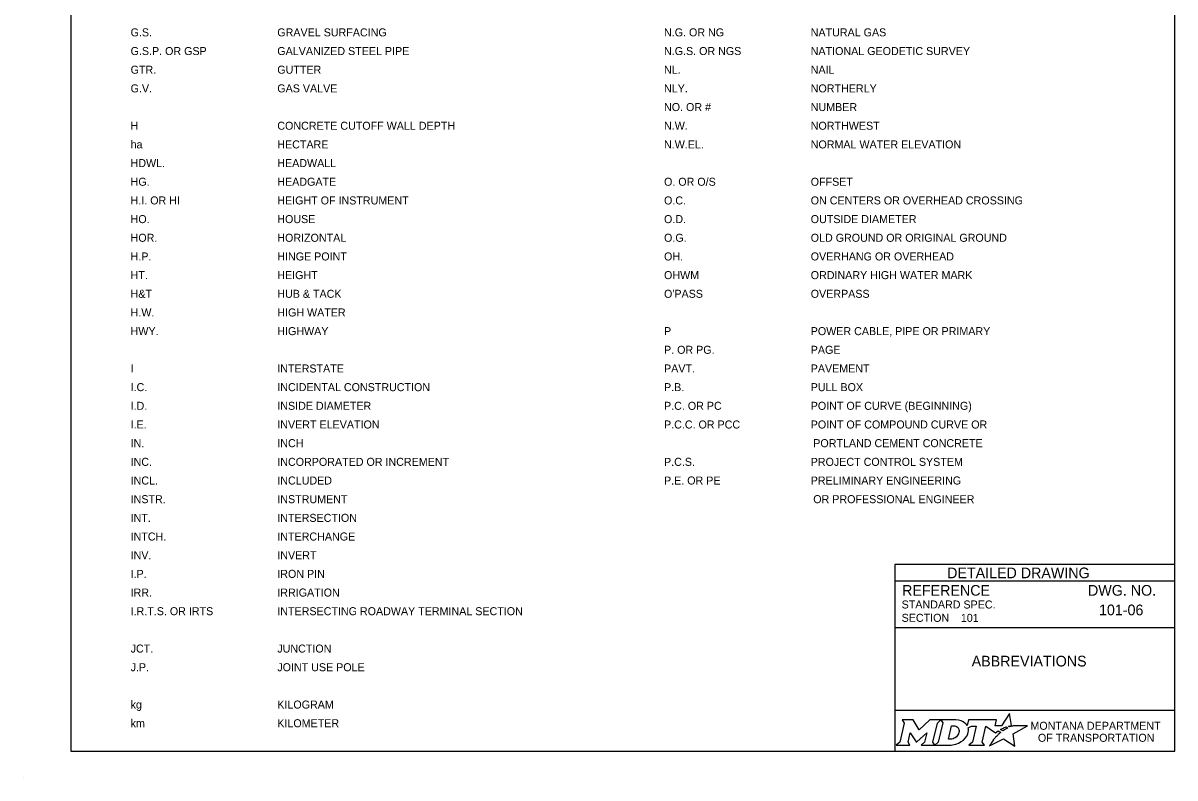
# Model space of a CAD drawing. Extents: x 49991.4 to 50021, y 49987.6 to 50011.4.
# Drawn here: x 49999.98 to 50008.61, y 49999.86 to 50005.52 of the extents above; entities that cross this region are included whole.
import ezdxf

# ---------------------------------------------------------------- set-up
doc = ezdxf.new("R2010")
doc.units = 0
for name, color, linetype in [('Default', 7, 'Continuous'), ('Level 1', 7, 'Continuous'), ('Level 2', 7, 'Continuous'), ('Level 5', 7, 'Continuous')]:
    doc.layers.add(name, color=color, linetype=linetype)

msp = doc.modelspace()

# ---------------------------------------------------------------- linework, layer by layer
at = {"layer": 'Default'}
msp.add_line((50007.719, 50000.7574), (50007.719, 50000.7574), dxfattribs=at)
at = {"layer": 'Level 1'}
msp.add_line((49999.9766, 49999.8624), (49999.9766, 49999.8624), dxfattribs=at)
msp.add_lwpolyline([(50008.6146, 50011.2628), (50000.3356, 50011.2628), (50000.3356, 50000.0624), (50008.6146, 50000.0624)], close=True, dxfattribs=at)
at = {"layer": 'Level 2'}
for p, q in [((50008.6146, 50001.4624), (50006.5146, 50001.4624)), ((50006.5146, 50001.4624), (50006.5146, 50000.0624)), ((50008.6146, 50001.3374), (50006.5146, 50001.3374)), ((50008.2507, 50001.1223), (50008.2507, 50001.1223)), ((50008.6146, 50000.9874), (50006.5146, 50000.9874)), ((50007.0089, 50001.0629), (50007.0089, 50001.0629)), ((50007.5646, 50000.7383), (50007.5646, 50000.7383)), ((50008.6146, 50000.3693), (50006.5146, 50000.3693))]:
    msp.add_line(p, q, dxfattribs=at)
for points in [[(50006.5701, 50000.2974), (50006.5842, 50000.274), (50006.5507, 50000.1307), (50006.525, 50000.1082), (50006.6266, 50000.1082), (50006.6131, 50000.131), (50006.6293, 50000.2011), (50006.673, 50000.1321), (50006.6783, 50000.1321), (50006.7534, 50000.2016), (50006.737, 50000.1305), (50006.7123, 50000.1085), (50006.8139, 50000.1085), (50006.8001, 50000.1318), (50006.8333, 50000.2742)], [(50006.8333, 50000.2742), (50006.8586, 50000.2974), (50006.7762, 50000.2974), (50006.6966, 50000.2244), (50006.6521, 50000.2971), (50006.5701, 50000.2974)], [(50006.9722, 50000.2974), (50006.8586, 50000.2974), (50006.8733, 50000.2745), (50006.8394, 50000.1307), (50006.8139, 50000.1085), (50006.9245, 50000.1085)], [(50007.3771, 50000.2447), (50007.3668, 50000.2503), (50007.3784, 50000.2531), (50007.39, 50000.2551), (50007.3726, 50000.3452), (50007.3131, 50000.2539), (50007.2658, 50000.2532), (50007.2761, 50000.2973), (50007.0669, 50000.2974), (50007.0568, 50000.2549), (50007.051, 50000.2632)], [(50006.9962, 50000.2107), (50006.995, 50000.2026), (50006.9918, 50000.1933), (50006.9876, 50000.1851), (50006.982, 50000.1776), (50006.9755, 50000.1707), (50006.9676, 50000.1644), (50006.9593, 50000.1597), (50006.9502, 50000.1558), (50006.9411, 50000.1535), (50006.9319, 50000.1526), (50006.916, 50000.1526), (50006.9396, 50000.2526), (50006.9556, 50000.2526), (50006.9632, 50000.252), (50006.9708, 50000.2501), (50006.9774, 50000.2471), (50006.9835, 50000.2429), (50006.9883, 50000.2379), (50006.992, 50000.2319), (50006.9947, 50000.2257), (50006.9963, 50000.2183), (50006.9963, 50000.2153), (50006.9962, 50000.2107)], [(50007.0636, 50000.2383), (50007.0882, 50000.2514), (50007.1251, 50000.2514), (50007.0965, 50000.1309), (50007.069, 50000.1082), (50007.1852, 50000.1082), (50007.1682, 50000.1311), (50007.1964, 50000.2513), (50007.2677, 50000.1996), (50007.2888, 50000.2147), (50007.3085, 50000.2038)], [(50007.2527, 50000.1479), (50007.2374, 50000.1235), (50007.2327, 50000.116), (50007.2269, 50000.1074), (50007.2246, 50000.1031), (50007.3299, 50000.1562), (50007.4138, 50000.1011), (50007.4007, 50000.1938), (50007.5076, 50000.2522), (50007.4583, 50000.253), (50007.4282, 50000.2534), (50007.4074, 50000.2537), (50007.4006, 50000.2522), (50007.3957, 50000.251), (50007.3873, 50000.2487), (50007.3771, 50000.2447)], [(50007.3267, 50000.2171), (50007.3243, 50000.2154), (50007.306, 50000.225), (50007.3163, 50000.2307), (50007.3204, 50000.2329), (50007.329, 50000.2369), (50007.3347, 50000.2395), (50007.3426, 50000.2425), (50007.3499, 50000.2452), (50007.3617, 50000.2378), (50007.3577, 50000.2357), (50007.3531, 50000.2332), (50007.3489, 50000.231), (50007.3439, 50000.2281), (50007.342, 50000.227), (50007.3393, 50000.2254), (50007.3368, 50000.224), (50007.3345, 50000.2224), (50007.3319, 50000.2206), (50007.3292, 50000.2188), (50007.3267, 50000.2171)], [(50006.9702, 50000.1158), (50006.9786, 50000.1184), (50006.9916, 50000.1238), (50007.012, 50000.1348)], [(50007.2666, 50000.164), (50007.2666, 50000.164)]]:
    msp.add_lwpolyline(points, dxfattribs=at)
for centre, radius, start, end in [((50006.9953, 50000.219), 0.0709, 339.53292, 15.85821), ((50006.9513, 50000.2363), 0.1183, 300.91025, 339.13831)]:
    msp.add_arc(centre, radius, start, end, dxfattribs=at)
for centre, major_axis, ratio, start_param, end_param in [((50006.9701, 50000.25), (0.0834, -0.0037), 0.568097, 0.61298, 1.570796), ((50007.0257, 50000.2573), (0.0361, -0.0295), 0.469099, 1.225588, 1.570796), ((50007.2974, 50000.1941), (-0.0112, -0.0097), 0.021651, 3.157348, 6.283185), ((50006.9248, 50000.2568), (0, 0.1484), 0.987302, 3.139398, 3.456847), ((50007.2597, 50000.1559), (-0.00694, -0.00806), 0.008222, 0, 3.137361), ((50007.2764, 50000.1742), (-0.0098, -0.0102), 0.016458, 3.141593, 6.279097)]:
    msp.add_ellipse(centre, major_axis=major_axis, ratio=ratio, start_param=start_param, end_param=end_param, dxfattribs=at)

# ---------------------------------------------------------------- texts
for s, height, p in [('G.S.           ', 0.06, (50000.7833, 50005.4226)), ('GRAVEL SURFACING                        ', 0.06, (50001.8833, 50005.4226)), ('N.G. OR NG     ', 0.06, (50004.7833, 50005.4226)), ('NATURAL GAS                             ', 0.06, (50005.8833, 50005.4226)), ('G.S.P. OR GSP  ', 0.06, (50000.7833, 50005.2826)), ('GALVANIZED STEEL PIPE                   ', 0.06, (50001.8833, 50005.2826)), ('N.G.S. OR NGS  ', 0.06, (50004.7833, 50005.2826)), ('NATIONAL GEODETIC SURVEY                ', 0.06, (50005.8833, 50005.2826)), ('GTR.           ', 0.06, (50000.7833, 50005.1426)), ('GUTTER                                  ', 0.06, (50001.8833, 50005.1426)), ('NL.            ', 0.06, (50004.7833, 50005.1426)), ('NAIL                                    ', 0.06, (50005.8833, 50005.1426)), ('G.V.           ', 0.06, (50000.7833, 50005.0026)), ('GAS VALVE                               ', 0.06, (50001.8833, 50005.0026)), ('NLY.           ', 0.06, (50004.7833, 50005.0026)), ('NORTHERLY                               ', 0.06, (50005.8833, 50005.0026)), ('NO. OR #       ', 0.06, (50004.7833, 50004.8626)), ('NUMBER                                  ', 0.06, (50005.8833, 50004.8626)), ('H          ', 0.06, (50000.7833, 50004.7226)), ('CONCRETE CUTOFF WALL DEPTH                              ', 0.06, (50001.8833, 50004.7226)), ('N.W.           ', 0.06, (50004.7833, 50004.7226)), ('NORTHWEST                               ', 0.06, (50005.8833, 50004.7226)), ('ha             ', 0.06, (50000.7833, 50004.5826)), ('HECTARE                                 ', 0.06, (50001.8833, 50004.5826)), ('N.W.EL.        ', 0.06, (50004.7833, 50004.5826)), ('NORMAL WATER ELEVATION                  ', 0.06, (50005.8833, 50004.5826)), ('HDWL.          ', 0.06, (50000.7833, 50004.4426)), ('HEADWALL                                ', 0.06, (50001.8833, 50004.4426)), ('HG.            ', 0.06, (50000.7833, 50004.3026)), ('HEADGATE                                ', 0.06, (50001.8833, 50004.3026)), ('O. OR O/S      ', 0.06, (50004.7833, 50004.3026)), ('OFFSET                                  ', 0.06, (50005.8833, 50004.3026)), ('H.I. OR HI     ', 0.06, (50000.7833, 50004.1626)), ('HEIGHT OF INSTRUMENT                    ', 0.06, (50001.8833, 50004.1626)), ('O.C.           ', 0.06, (50004.7833, 50004.1626)), ('ON CENTERS OR OVERHEAD CROSSING         ', 0.06, (50005.8833, 50004.1626)), ('HO.            ', 0.06, (50000.7833, 50004.0226)), ('HOUSE                                   ', 0.06, (50001.8833, 50004.0226)), ('O.D.           ', 0.06, (50004.7833, 50004.0226)), ('OUTSIDE DIAMETER                        ', 0.06, (50005.8833, 50004.0226)), ('HOR.           ', 0.06, (50000.7833, 50003.8826)), ('HORIZONTAL                              ', 0.06, (50001.8833, 50003.8826)), ('O.G.           ', 0.06, (50004.7833, 50003.8826)), ('OLD GROUND OR ORIGINAL GROUND           ', 0.06, (50005.8833, 50003.8826)), ('H.P.           ', 0.06, (50000.7833, 50003.7426)), ('HINGE POINT                             ', 0.06, (50001.8833, 50003.7426)), ('OH.            ', 0.06, (50004.7833, 50003.7426)), ('OVERHANG OR OVERHEAD                    ', 0.06, (50005.8833, 50003.7426)), ('HT.            ', 0.06, (50000.7833, 50003.6026)), ('HEIGHT                                  ', 0.06, (50001.8833, 50003.6026)), ('OHWM         ', 0.06, (50004.7833, 50003.6026)), ('ORDINARY HIGH WATER MARK                               ', 0.06, (50005.8833, 50003.6026)), ('H&T            ', 0.06, (50000.7833, 50003.4626)), ('HUB & TACK                              ', 0.06, (50001.8833, 50003.4626)), ("O'PASS         ", 0.06, (50004.7833, 50003.4626)), ('OVERPASS                                ', 0.06, (50005.8833, 50003.4626)), ('H.W.           ', 0.06, (50000.7833, 50003.3226)), ('HIGH WATER                              ', 0.06, (50001.8833, 50003.3226)), ('HWY.           ', 0.06, (50000.7833, 50003.1826)), ('HIGHWAY                                 ', 0.06, (50001.8833, 50003.1826)), ('P              ', 0.06, (50004.7833, 50003.1826)), ('POWER CABLE, PIPE OR PRIMARY            ', 0.06, (50005.8833, 50003.1826)), ('P. OR PG.      ', 0.06, (50004.7833, 50003.0426)), ('PAGE                                    ', 0.06, (50005.8833, 50003.0426)), ('INTERSTATE                              ', 0.06, (50001.8833, 50002.9026)), ('I              ', 0.06, (50000.7833, 50002.9026)), ('PAVT.          ', 0.06, (50004.7833, 50002.9026)), ('PAVEMENT                                ', 0.06, (50005.8833, 50002.9026)), ('I.C.           ', 0.06, (50000.7833, 50002.7626)), ('INCIDENTAL CONSTRUCTION                 ', 0.06, (50001.8833, 50002.7626)), ('P.B.           ', 0.06, (50004.7833, 50002.7626)), ('PULL BOX                                ', 0.06, (50005.8833, 50002.7626)), ('I.D.           ', 0.06, (50000.7833, 50002.6226)), ('INSIDE DIAMETER                         ', 0.06, (50001.8833, 50002.6226)), ('P.C. OR PC     ', 0.06, (50004.7833, 50002.6226)), ('POINT OF CURVE (BEGINNING)              ', 0.06, (50005.8833, 50002.6226)), ('I.E.           ', 0.06, (50000.7833, 50002.4826)), ('INVERT ELEVATION                        ', 0.06, (50001.8833, 50002.4826)), ('P.C.C. OR PCC  ', 0.06, (50004.7833, 50002.4826)), ('POINT OF COMPOUND CURVE OR              ', 0.06, (50005.8833, 50002.4826)), ('IN.            ', 0.06, (50000.7833, 50002.3426)), ('INCH                                    ', 0.06, (50001.8833, 50002.3426)), ('   PORTLAND CEMENT CONCRETE             ', 0.06, (50005.8354, 50002.3426)), ('INC.           ', 0.06, (50000.7833, 50002.2026)), ('INCORPORATED OR INCREMENT               ', 0.06, (50001.8833, 50002.2026)), ('P.C.S.         ', 0.06, (50004.7833, 50002.2026)), ('PROJECT CONTROL SYSTEM                  ', 0.06, (50005.8833, 50002.2026)), ('INCL.          ', 0.06, (50000.7833, 50002.0626)), ('INCLUDED                                ', 0.06, (50001.8833, 50002.0626)), ('P.E. OR PE     ', 0.06, (50004.7833, 50002.0626)), ('PRELIMINARY ENGINEERING                         ', 0.06, (50005.8833, 50002.0626)), ('INSTR.         ', 0.06, (50000.7833, 50001.9226)), ('INSTRUMENT                              ', 0.06, (50001.8833, 50001.9226)), ('   OR PROFESSIONAL ENGINEER                     ', 0.06, (50005.8354, 50001.9226)), ('INT.           ', 0.06, (50000.7833, 50001.7826)), ('INTERSECTION                            ', 0.06, (50001.8833, 50001.7826)), ('INTCH.         ', 0.06, (50000.7833, 50001.6426)), ('INTERCHANGE                             ', 0.06, (50001.8833, 50001.6426)), ('INV.           ', 0.06, (50000.7833, 50001.5026)), ('INVERT                                  ', 0.06, (50001.8833, 50001.5026)), ('I.P.           ', 0.06, (50000.7833, 50001.3626)), ('IRON PIN                                ', 0.06, (50001.8833, 50001.3626)), ('IRR.           ', 0.06, (50000.7833, 50001.2226)), ('IRRIGATION                              ', 0.06, (50001.8833, 50001.2226)), ('REFERENCE', 0.08, (50006.5682, 50001.229)), ('DWG. NO.', 0.08, (50007.9624, 50001.229)), ('STANDARD SPEC.', 0.06, (50006.5649, 50001.133)), ('101-06', 0.08, (50008.0449, 50001.0823)), ('I.R.T.S. OR IRTS', 0.06, (50000.7833, 50001.0826)), ('INTERSECTING ROADWAY TERMINAL SECTION   ', 0.06, (50001.8833, 50001.0826)), ('SECTION', 0.06, (50006.5649, 50001.033)), ('101', 0.06, (50007.0089, 50001.0329)), ('JCT.           ', 0.06, (50000.7833, 50000.8026)), ('JUNCTION                                ', 0.06, (50001.8833, 50000.8026)), ('J.P.           ', 0.06, (50000.7833, 50000.6626)), ('JOINT USE POLE                          ', 0.06, (50001.8833, 50000.6626)), ('ABBREVIATIONS', 0.08, (50007.09, 50000.6983)), ('kg             ', 0.06, (50000.7833, 50000.3826)), ('KILOGRAM                                ', 0.06, (50001.8833, 50000.3826)), ('km            ', 0.06, (50000.7833, 50000.2426)), ('KILOMETER                              ', 0.06, (50001.8833, 50000.2426)), ('MONTANA DEPARTMENT', 0.06, (50007.5308, 50000.2236)), ('OF TRANSPORTATION', 0.06, (50007.587, 50000.1336))]:
    msp.add_text(s, height=height, dxfattribs=at).set_placement(p)
at = {"layer": 'Level 5'}
msp.add_text('DETAILED DRAWING', height=0.0799, dxfattribs=at).set_placement((50006.9063, 50001.3599))

doc.saveas('drawing.dxf')
